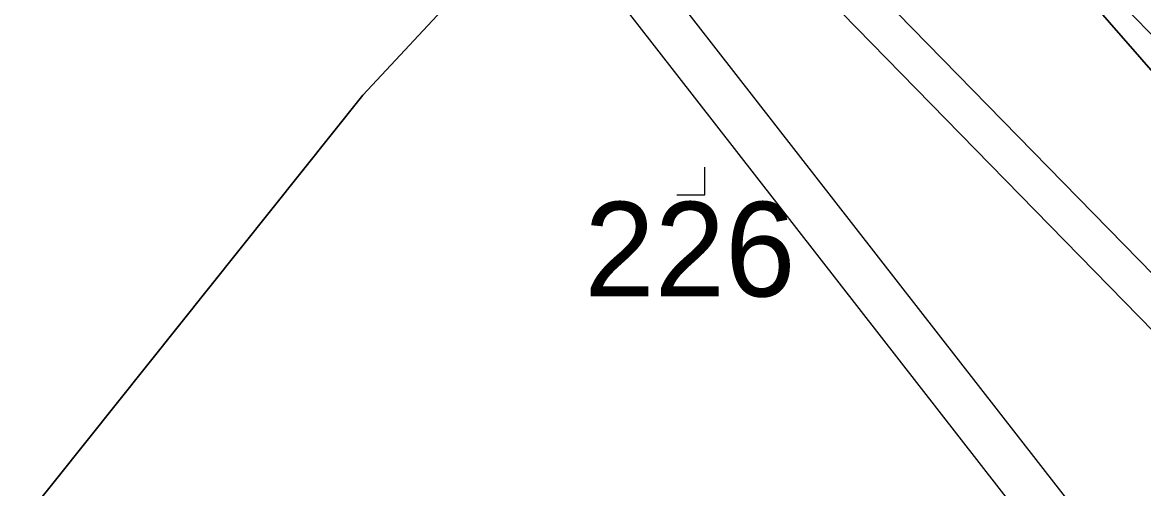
# Model space of a CAD drawing. Extents: x -537341 to -532984, y -1143469 to -1141314.
# Drawn here: x -535859.69 to -535819.4, y -1143083.43 to -1143066.67 of the extents above; entities that cross this region are included whole.
import ezdxf

# ---------------------------------------------------------------- set-up
doc = ezdxf.new("R2010")
doc.units = 0
for name, color, linetype in [('Hranice parcel', 7, 'Continuous'), ('parcelní_č_2000', 7, 'Continuous'), ('u_arcibiskupství', 7, 'Continuous'), ('u_obec_Horní_Moš', 7, 'Continuous'), ('u_pricne', 7, 'Continuous'), ('u_úřad pro_zast', 7, 'Continuous'), ('Značky kultur', 7, 'Continuous')]:
    doc.layers.add(name, color=color, linetype=linetype)

msp = doc.modelspace()

# ---------------------------------------------------------------- linework, layer by layer
at = {"layer": 'Hranice parcel'}
for points in [[(-535872.47, -1143100.32), (-535867.33, -1143094.17), (-535847.45, -1143069.28), (-535833.42, -1143054.22)], [(-535810.41, -1143077.74), (-535814.9, -1143073.23), (-535821.79, -1143065.33), (-535833.42, -1143054.22)]]:
    msp.add_lwpolyline(points, dxfattribs=at)
at = {"layer": 'u_arcibiskupství'}
msp.add_lwpolyline([(-535833.42, -1143054.22), (-535821.79, -1143065.33), (-535814.9, -1143073.23), (-535810.41, -1143077.74)], dxfattribs=at)
at = {"layer": 'u_obec_Horní_Moš'}
msp.add_lwpolyline([(-535872.149, -1143099.936), (-535867.33, -1143094.17), (-535847.45, -1143069.28), (-535833.42, -1143054.22)], dxfattribs=at)
at = {"layer": 'u_pricne'}
for p, q in [((-535876.24, -1143008.636), (-535783.378, -1143103.693)), ((-535878.97, -1143010.837), (-535797.695, -1143115.233)), ((-535880.28, -1143011.892), (-535799.004, -1143116.289)), ((-535880.922, -1143012.41), (-535788.06, -1143107.467)), ((-535882.033, -1143013.305), (-535789.171, -1143108.363))]:
    msp.add_line(p, q, dxfattribs=at)
at = {"layer": 'u_úřad pro_zast'}
for points in [[(-535833.42, -1143054.22), (-535847.45, -1143069.28), (-535867.33, -1143094.17)], [(-535814.9, -1143073.23), (-535821.79, -1143065.33), (-535833.42, -1143054.22)]]:
    msp.add_lwpolyline(points, dxfattribs=at)
at = {"layer": 'Značky kultur'}
for p, q in [((-535835.17, -1143072.87), (-535835.17, -1143071.87)), ((-535835.17, -1143072.87), (-535835.17, -1143071.87)), ((-535836.171, -1143072.87), (-535835.17, -1143072.87)), ((-535836.171, -1143072.87), (-535835.17, -1143072.87))]:
    msp.add_line(p, q, dxfattribs=at)

# ---------------------------------------------------------------- texts
at = {"layer": 'parcelní_č_2000'}
msp.add_text('226', height=3.4, dxfattribs=at).set_placement((-535839.495, -1143076.52))

doc.saveas('drawing.dxf')
